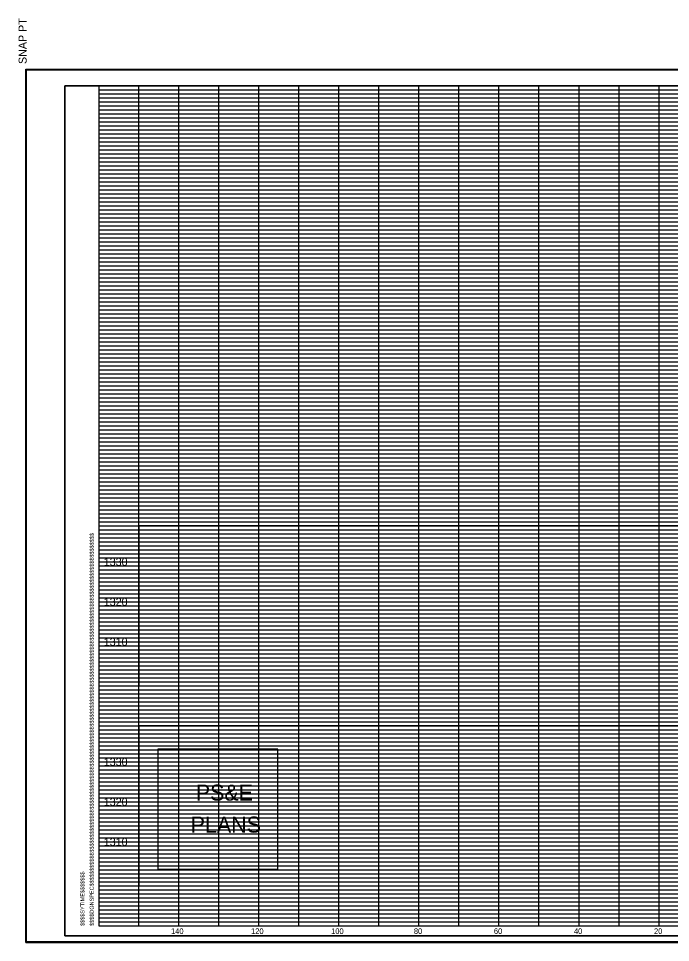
# Model space of a CAD drawing. Extents: x 130 to 1324, y -58 to 2657.
# Drawn here: x 979.9 to 1142.9, y 1265.9 to 1496.8 of the extents above; entities that cross this region are included whole.
import ezdxf

# ---------------------------------------------------------------- set-up
doc = ezdxf.new("R2010")
doc.units = 0
for name, color, linetype in [('DESIGN - SCRATCH - User 2', 7, 'Continuous'), ('DESIGN - SHEET - Corner Text', 7, 'Continuous'), ('DESIGN - SHEET - Light Grid', 7, 'Continuous'), ('DESIGN - SHEET - Linework', 7, 'Continuous'), ('DESIGN - SHEET - Plot Shape', 7, 'Continuous'), ('DESIGN - TYPICAL - Finished Grade and Subgrade', 7, 'Continuous')]:
    doc.layers.add(name, color=color, linetype=linetype)

# ---------------------------------------------------------------- blocks, each defined once
blk = doc.blocks.new('XSTSHT')
at = {"layer": 'DESIGN - SHEET - Light Grid'}
for p, q in [((0, 20.9), (8, 20.9)), ((0, 20.8), (8, 20.8)), ((8, 20.9), (16, 20.9)), ((8, 20.8), (16, 20.8)), ((0, 20.7), (8, 20.7)), ((0, 20.6), (8, 20.6)), ((8, 20.7), (16, 20.7)), ((8, 20.6), (16, 20.6)), ((0, 20.5), (8, 20.5)), ((0, 20.4), (8, 20.4)), ((8, 20.5), (16, 20.5)), ((8, 20.4), (16, 20.4)), ((0, 20.3), (8, 20.3)), ((0, 20.2), (8, 20.2)), ((0, 20.1), (8, 20.1)), ((8, 20.3), (16, 20.3)), ((8, 20.2), (16, 20.2)), ((8, 20.1), (16, 20.1)), ((0, 19.9), (8, 19.9)), ((8, 19.9), (16, 19.9)), ((0, 19.8), (8, 19.8)), ((0, 19.7), (8, 19.7)), ((8, 19.8), (16, 19.8)), ((8, 19.7), (16, 19.7)), ((0, 19.6), (8, 19.6)), ((0, 19.5), (8, 19.5)), ((0, 19.4), (8, 19.4)), ((8, 19.6), (16, 19.6)), ((8, 19.5), (16, 19.5)), ((8, 19.4), (16, 19.4)), ((0, 19.3), (8, 19.3)), ((0, 19.2), (8, 19.2)), ((8, 19.3), (16, 19.3)), ((8, 19.2), (16, 19.2)), ((0, 19.1), (8, 19.1)), ((8, 19.1), (16, 19.1)), ((0, 18.9), (8, 18.9)), ((0, 18.8), (8, 18.8)), ((8, 18.9), (16, 18.9)), ((8, 18.8), (16, 18.8)), ((0, 18.7), (8, 18.7)), ((0, 18.6), (8, 18.6)), ((0, 18.5), (8, 18.5)), ((8, 18.7), (16, 18.7)), ((8, 18.6), (16, 18.6)), ((8, 18.5), (16, 18.5)), ((0, 18.4), (8, 18.4)), ((0, 18.3), (8, 18.3)), ((8, 18.4), (16, 18.4)), ((8, 18.3), (16, 18.3)), ((0, 18.2), (8, 18.2)), ((0, 18.1), (8, 18.1)), ((8, 18.2), (16, 18.2)), ((8, 18.1), (16, 18.1)), ((0, 17.9), (8, 17.9)), ((0, 17.8), (8, 17.8)), ((8, 17.9), (16, 17.9)), ((8, 17.8), (16, 17.8)), ((0, 17.7), (8, 17.7)), ((0, 17.6), (8, 17.6)), ((8, 17.7), (16, 17.7)), ((8, 17.6), (16, 17.6)), ((0, 17.5), (8, 17.5)), ((0, 17.4), (8, 17.4)), ((8, 17.5), (16, 17.5)), ((8, 17.4), (16, 17.4)), ((0, 17.3), (8, 17.3)), ((0, 17.2), (8, 17.2)), ((0, 17.1), (8, 17.1)), ((8, 17.3), (16, 17.3)), ((8, 17.2), (16, 17.2)), ((8, 17.1), (16, 17.1)), ((0, 16.9), (8, 16.9)), ((8, 16.9), (16, 16.9)), ((0, 16.8), (8, 16.8)), ((0, 16.7), (8, 16.7)), ((8, 16.8), (16, 16.8)), ((8, 16.7), (16, 16.7)), ((0, 16.6), (8, 16.6)), ((0, 16.5), (8, 16.5)), ((0, 16.4), (8, 16.4)), ((8, 16.6), (16, 16.6)), ((8, 16.5), (16, 16.5)), ((8, 16.4), (16, 16.4)), ((0, 16.3), (8, 16.3)), ((0, 16.2), (8, 16.2)), ((8, 16.3), (16, 16.3)), ((8, 16.2), (16, 16.2)), ((0, 16.1), (8, 16.1)), ((8, 16.1), (16, 16.1)), ((0, 15.9), (8, 15.9)), ((0, 15.8), (8, 15.8)), ((8, 15.9), (16, 15.9)), ((8, 15.8), (16, 15.8)), ((0, 15.7), (8, 15.7)), ((0, 15.6), (8, 15.6)), ((0, 15.5), (8, 15.5)), ((8, 15.7), (16, 15.7)), ((8, 15.6), (16, 15.6)), ((8, 15.5), (16, 15.5)), ((0, 15.4), (8, 15.4)), ((0, 15.3), (8, 15.3)), ((8, 15.4), (16, 15.4)), ((8, 15.3), (16, 15.3)), ((0, 15.2), (8, 15.2)), ((0, 15.1), (8, 15.1)), ((8, 15.2), (16, 15.2)), ((8, 15.1), (16, 15.1)), ((0, 14.9), (8, 14.9)), ((0, 14.8), (8, 14.8)), ((8, 14.9), (16, 14.9)), ((8, 14.8), (16, 14.8)), ((0, 14.7), (8, 14.7)), ((0, 14.6), (8, 14.6)), ((8, 14.7), (16, 14.7)), ((8, 14.6), (16, 14.6)), ((0, 14.5), (8, 14.5)), ((0, 14.4), (8, 14.4)), ((8, 14.5), (16, 14.5)), ((8, 14.4), (16, 14.4)), ((0, 14.3), (8, 14.3)), ((0, 14.2), (8, 14.2)), ((0, 14.1), (8, 14.1)), ((8, 14.3), (16, 14.3)), ((8, 14.2), (16, 14.2)), ((8, 14.1), (16, 14.1)), ((0, 13.9), (8, 13.9)), ((8, 13.9), (16, 13.9)), ((0, 13.8), (8, 13.8)), ((0, 13.7), (8, 13.7)), ((8, 13.8), (16, 13.8)), ((8, 13.7), (16, 13.7)), ((0, 13.6), (8, 13.6)), ((0, 13.5), (8, 13.5)), ((0, 13.4), (8, 13.4)), ((8, 13.6), (16, 13.6)), ((8, 13.5), (16, 13.5)), ((8, 13.4), (16, 13.4)), ((0, 13.3), (8, 13.3)), ((0, 13.2), (8, 13.2)), ((8, 13.3), (16, 13.3)), ((8, 13.2), (16, 13.2)), ((0, 13.1), (8, 13.1)), ((8, 13.1), (16, 13.1)), ((0, 12.9), (8, 12.9)), ((0, 12.8), (8, 12.8)), ((8, 12.9), (16, 12.9)), ((8, 12.8), (16, 12.8)), ((0, 12.7), (8, 12.7)), ((0, 12.6), (8, 12.6)), ((0, 12.5), (8, 12.5)), ((8, 12.7), (16, 12.7)), ((8, 12.6), (16, 12.6)), ((8, 12.5), (16, 12.5)), ((0, 12.4), (8, 12.4)), ((0, 12.3), (8, 12.3)), ((8, 12.4), (16, 12.4)), ((8, 12.3), (16, 12.3)), ((0, 12.2), (8, 12.2)), ((0, 12.1), (8, 12.1)), ((8, 12.2), (16, 12.2)), ((8, 12.1), (16, 12.1)), ((0, 11.9), (8, 11.9)), ((0, 11.8), (8, 11.8)), ((8, 11.9), (16, 11.9)), ((8, 11.8), (16, 11.8)), ((0, 11.7), (8, 11.7)), ((0, 11.6), (8, 11.6)), ((8, 11.7), (16, 11.7)), ((8, 11.6), (16, 11.6)), ((0, 11.5), (8, 11.5)), ((0, 11.4), (8, 11.4)), ((8, 11.5), (16, 11.5)), ((8, 11.4), (16, 11.4)), ((0, 11.3), (8, 11.3)), ((0, 11.2), (8, 11.2)), ((0, 11.1), (8, 11.1)), ((8, 11.3), (16, 11.3)), ((8, 11.2), (16, 11.2)), ((8, 11.1), (16, 11.1)), ((0, 10.9), (8, 10.9)), ((8, 10.9), (16, 10.9)), ((0, 10.8), (8, 10.8)), ((0, 10.7), (8, 10.7)), ((8, 10.8), (16, 10.8)), ((8, 10.7), (16, 10.7)), ((0, 10.6), (8, 10.6)), ((0, 10.5), (8, 10.5)), ((0, 10.4), (8, 10.4)), ((8, 10.6), (16, 10.6)), ((8, 10.5), (16, 10.5)), ((8, 10.4), (16, 10.4)), ((0, 10.3), (8, 10.3)), ((0, 10.2), (8, 10.2)), ((8, 10.3), (16, 10.3)), ((8, 10.2), (16, 10.2)), ((0, 10.1), (8, 10.1)), ((8, 10.1), (16, 10.1)), ((0, 9.9), (8, 9.9)), ((0, 9.8), (8, 9.8)), ((0, 9.7), (8, 9.7)), ((8, 9.9), (16, 9.9)), ((8, 9.8), (16, 9.8)), ((8, 9.7), (16, 9.7)), ((0, 9.6), (8, 9.6)), ((0, 9.5), (8, 9.5)), ((8, 9.6), (16, 9.6)), ((8, 9.5), (16, 9.5)), ((0, 9.4), (8, 9.4)), ((0, 9.3), (8, 9.3)), ((8, 9.4), (16, 9.4)), ((8, 9.3), (16, 9.3)), ((0, 9.2), (8, 9.2)), ((0, 9.1), (8, 9.1)), ((8, 9.2), (16, 9.2)), ((8, 9.1), (16, 9.1)), ((0, 8.9), (8, 8.9)), ((0, 8.8), (8, 8.8)), ((8, 8.9), (16, 8.9)), ((8, 8.8), (16, 8.8)), ((0, 8.7), (8, 8.7)), ((0, 8.6), (8, 8.6)), ((8, 8.7), (16, 8.7)), ((8, 8.6), (16, 8.6)), ((0, 8.5), (8, 8.5)), ((0, 8.4), (8, 8.4)), ((8, 8.5), (16, 8.5)), ((8, 8.4), (16, 8.4)), ((0, 8.3), (8, 8.3)), ((0, 8.2), (8, 8.2)), ((0, 8.1), (8, 8.1)), ((8, 8.3), (16, 8.3)), ((8, 8.2), (16, 8.2)), ((8, 8.1), (16, 8.1)), ((0, 7.9), (8, 7.9)), ((8, 7.9), (16, 7.9)), ((0, 7.8), (8, 7.8)), ((0, 7.7), (8, 7.7)), ((8, 7.8), (16, 7.8)), ((8, 7.7), (16, 7.7)), ((0, 7.6), (8, 7.6)), ((0, 7.5), (8, 7.5)), ((0, 7.4), (8, 7.4)), ((8, 7.6), (16, 7.6)), ((8, 7.5), (16, 7.5)), ((8, 7.4), (16, 7.4)), ((0, 7.3), (8, 7.3)), ((0, 7.2), (8, 7.2)), ((8, 7.3), (16, 7.3)), ((8, 7.2), (16, 7.2)), ((0, 7.1), (8, 7.1)), ((8, 7.1), (16, 7.1)), ((0, 6.9), (8, 6.9)), ((0, 6.8), (8, 6.8)), ((0, 6.7), (8, 6.7)), ((8, 6.9), (16, 6.9)), ((8, 6.8), (16, 6.8)), ((8, 6.7), (16, 6.7)), ((0, 6.6), (8, 6.6)), ((0, 6.5), (8, 6.5)), ((8, 6.6), (16, 6.6)), ((8, 6.5), (16, 6.5)), ((0, 6.4), (8, 6.4)), ((0, 6.3), (8, 6.3)), ((8, 6.4), (16, 6.4)), ((8, 6.3), (16, 6.3)), ((0, 6.2), (8, 6.2)), ((0, 6.1), (8, 6.1)), ((8, 6.2), (16, 6.2)), ((8, 6.1), (16, 6.1)), ((0, 5.9), (8, 5.9)), ((0, 5.8), (8, 5.8)), ((8, 5.9), (16, 5.9)), ((8, 5.8), (16, 5.8)), ((0, 5.7), (8, 5.7)), ((0, 5.6), (8, 5.6)), ((8, 5.7), (16, 5.7)), ((8, 5.6), (16, 5.6)), ((0, 5.5), (8, 5.5)), ((0, 5.4), (8, 5.4)), ((8, 5.5), (16, 5.5)), ((8, 5.4), (16, 5.4)), ((0, 5.3), (8, 5.3)), ((0, 5.2), (8, 5.2)), ((0, 5.1), (8, 5.1)), ((8, 5.3), (16, 5.3)), ((8, 5.2), (16, 5.2)), ((8, 5.1), (16, 5.1)), ((0, 4.9), (8, 4.9)), ((8, 4.9), (16, 4.9)), ((0, 4.8), (8, 4.8)), ((0, 4.7), (8, 4.7)), ((8, 4.8), (16, 4.8)), ((8, 4.7), (16, 4.7)), ((0, 4.6), (8, 4.6)), ((0, 4.5), (8, 4.5)), ((0, 4.4), (8, 4.4)), ((8, 4.6), (16, 4.6)), ((8, 4.5), (16, 4.5)), ((8, 4.4), (16, 4.4)), ((0, 4.3), (8, 4.3)), ((0, 4.2), (8, 4.2)), ((8, 4.3), (16, 4.3)), ((8, 4.2), (16, 4.2)), ((0, 4.1), (8, 4.1)), ((8, 4.1), (16, 4.1)), ((0, 3.9), (8, 3.9)), ((0, 3.8), (8, 3.8)), ((0, 3.7), (8, 3.7)), ((8, 3.9), (16, 3.9)), ((8, 3.8), (16, 3.8)), ((8, 3.7), (16, 3.7)), ((0, 3.6), (8, 3.6)), ((0, 3.5), (8, 3.5)), ((8, 3.6), (16, 3.6)), ((8, 3.5), (16, 3.5)), ((0, 3.4), (8, 3.4)), ((0, 3.3), (8, 3.3)), ((8, 3.4), (16, 3.4)), ((8, 3.3), (16, 3.3)), ((0, 3.2), (8, 3.2)), ((0, 3.1), (8, 3.1)), ((8, 3.2), (16, 3.2)), ((8, 3.1), (16, 3.1)), ((0, 2.9), (8, 2.9)), ((0, 2.8), (8, 2.8)), ((8, 2.9), (16, 2.9)), ((8, 2.8), (16, 2.8)), ((0, 2.7), (8, 2.7)), ((0, 2.6), (8, 2.6)), ((8, 2.7), (16, 2.7)), ((8, 2.6), (16, 2.6)), ((0, 2.5), (8, 2.5)), ((0, 2.4), (8, 2.4)), ((8, 2.5), (16, 2.5)), ((8, 2.4), (16, 2.4)), ((0, 2.3), (8, 2.3)), ((0, 2.2), (8, 2.2)), ((0, 2.1), (8, 2.1)), ((8, 2.3), (16, 2.3)), ((8, 2.2), (16, 2.2)), ((8, 2.1), (16, 2.1)), ((0, 1.9), (8, 1.9)), ((8, 1.9), (16, 1.9)), ((0, 1.8), (8, 1.8)), ((0, 1.7), (8, 1.7)), ((8, 1.8), (16, 1.8)), ((8, 1.7), (16, 1.7)), ((0, 1.6), (8, 1.6)), ((0, 1.5), (8, 1.5)), ((0, 1.4), (8, 1.4)), ((8, 1.6), (16, 1.6)), ((8, 1.5), (16, 1.5)), ((8, 1.4), (16, 1.4)), ((0, 1.3), (8, 1.3)), ((0, 1.2), (8, 1.2)), ((8, 1.3), (16, 1.3)), ((8, 1.2), (16, 1.2)), ((0, 1.1), (8, 1.1)), ((8, 1.1), (16, 1.1)), ((0, 0.9), (8, 0.9)), ((0, 0.8), (8, 0.8)), ((0, 0.7), (8, 0.7)), ((8, 0.9), (16, 0.9)), ((8, 0.8), (16, 0.8)), ((8, 0.7), (16, 0.7)), ((0, 0.6), (8, 0.6)), ((0, 0.5), (8, 0.5)), ((8, 0.6), (16, 0.6)), ((8, 0.5), (16, 0.5)), ((0, 0.4), (8, 0.4)), ((0, 0.3), (8, 0.3)), ((8, 0.4), (16, 0.4)), ((8, 0.3), (16, 0.3)), ((0, 0.2), (8, 0.2)), ((0, 0.1), (8, 0.1)), ((8, 0.2), (16, 0.2)), ((8, 0.1), (16, 0.1))]:
    blk.add_line(p, q, dxfattribs=at)
at = {"layer": 'DESIGN - SHEET - Linework'}
for p, q in [((-1.823, -0.414), (-1.823, 21.414)), ((-1.823, 21.414), (32.217, 21.414)), ((1, 0), (1, 21)), ((2, 0), (2, 21)), ((3, 0), (3, 21)), ((4, 0), (4, 21)), ((5, 0), (5, 21)), ((6, 0), (6, 21)), ((7, 0), (7, 21)), ((8, 0), (8, 21)), ((9, 0), (9, 21)), ((10, 0), (10, 21)), ((11, 0), (11, 21)), ((12, 0), (12, 21)), ((13, 0), (13, 21)), ((14, 0), (14, 21)), ((0, 20), (28, 20)), ((0, 19), (32, 19)), ((0, 18), (32, 18)), ((0, 17), (32, 17)), ((0, 16), (32, 16)), ((0, 15), (32, 15)), ((0, 14), (32, 14)), ((0, 13), (32, 13)), ((0, 12), (32, 12)), ((0, 11), (32, 11)), ((0, 10), (32, 10)), ((0, 9), (32, 9)), ((0, 8), (32, 8)), ((0, 7), (32, 7)), ((0, 6), (32, 6)), ((0, 5), (32, 5)), ((0, 4), (32, 4)), ((0, 3), (32, 3)), ((0, 2), (32, 2)), ((0, 1), (32, 1)), ((-1.823, -0.414), (32.217, -0.414))]:
    blk.add_line(p, q, dxfattribs=at)
blk.add_lwpolyline([(0, 21), (0, 0), (32, 0), (32, 21), (0, 21)], dxfattribs=at)
at = {"layer": 'DESIGN - SHEET - Plot Shape'}
for points in [[(-1.803, 21.394), (32.197, 21.394), (32.197, -0.394), (-1.803, -0.394)], [(-0.85, 21), (32, 21), (32, -0.25), (-0.85, -0.25)]]:
    blk.add_lwpolyline(points, close=True, dxfattribs=at)
at = {"layer": 'DESIGN - SHEET - Corner Text'}
for s, height, p in [('  SNAP PT', 0.2, (-1.803, 21.394)), ('$$$$DGNSPEC$$$$$$$$$$$$$$$$$$$$$$$$$$$$$$$$$$$$$$$$$$$$$$$$$$$$$$$$$$$$$$$$$$$$$$$$$$$$$$$$$$$$$$$$$$$$$$$$$$$$$$$$$$$$$$$$$$$', 0.100002, (-0.126, 0)), ('$$$$SYTIME$$$$$$$', 0.1, (-0.358, 0))]:
    blk.add_text(s, height=height, rotation=90, dxfattribs=at).set_placement(p)

msp = doc.modelspace()

# ---------------------------------------------------------------- linework, layer by layer
at = {"layer": 'DESIGN - SCRATCH - User 2'}
for points in [[(1010, 1330), (1310, 1330), (1310, 1370), (1010, 1370)], [(1010, 1280), (1310, 1280), (1310, 1320), (1010, 1320)]]:
    msp.add_lwpolyline(points, close=True, dxfattribs=at)
at = {"layer": 'DESIGN - SHEET - Corner Text'}
msp.add_lwpolyline([(1014.74, 1314.16), (1014.74, 1284.16), (1044.74, 1284.16), (1044.74, 1314.16)], close=True, dxfattribs=at)
at = {"layer": 'DESIGN - SHEET - Plot Shape'}
msp.add_lwpolyline([(991.5, 1267.5), (1320, 1267.5), (1320, 1480), (991.5, 1480)], close=True, dxfattribs=at)

# ---------------------------------------------------------------- block references
at = {"layer": 'DESIGN - TYPICAL - Finished Grade and Subgrade', "xscale": 10, "yscale": 10}
msp.add_blockref('XSTSHT', (1000, 1270), dxfattribs=at)

# ---------------------------------------------------------------- texts
at = {"layer": 'DESIGN - SHEET - Corner Text'}
for s, height, p in [('1330', 2, (1001.25, 1360)), ('1320', 2, (1001.25, 1350)), ('1310', 2, (1001.25, 1340)), ('1330', 2, (1001.25, 1310)), ('PS&E', 4, (1024.26, 1301.33)), ('1320', 2, (1001.25, 1300)), ('PLANS', 4, (1022.98, 1293.33)), ('1310', 2, (1001.25, 1290)), ('140', 1.4, (1018.06, 1268)), ('120', 1.4, (1038.06, 1268)), ('100', 1.4, (1058.06, 1268)), ('80', 1.4, (1078.74, 1268)), ('60', 1.4, (1098.74, 1268)), ('40', 1.4, (1118.74, 1268)), ('20', 1.4, (1138.74, 1268))]:
    msp.add_text(s, height=height, dxfattribs=at).set_placement(p)

doc.saveas('drawing.dxf')
